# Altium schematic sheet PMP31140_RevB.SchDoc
size 431 x 279 mm; Date: Not shown in title block; ApprovedBy: Not shown in title block; CheckedBy: Not shown in title block; Author: Not shown in title block; CompanyName: Not shown in title block; Engineer: Not shown in title block; Organization: Not shown in title block; Address1: Not shown in title block; Address2: Not shown in title block; Address3: Not shown in title block; Address4: Not shown in title block; DocumentNumber: 1; Revision: Use project parameter SCH_Rev; SheetNumber: 1; SheetTotal: 1; PageSetup: Record=PageOptions¦CenterHorizontal=True¦CenterVertical=True¦PrintScale=1.00¦XCorrection=1.00¦YCorrection=1.00¦PrintKind=0¦BorderSize=5000000¦LeftOffset=0¦BottomOffset=0¦Orientation=2¦PaperLength=1000¦PaperWidth=1000¦Scale=100¦PaperSource=15¦PrintQuality=600¦MediaType=1¦DitherType=10¦PaperKind=Letter¦PrintScaleMode=1
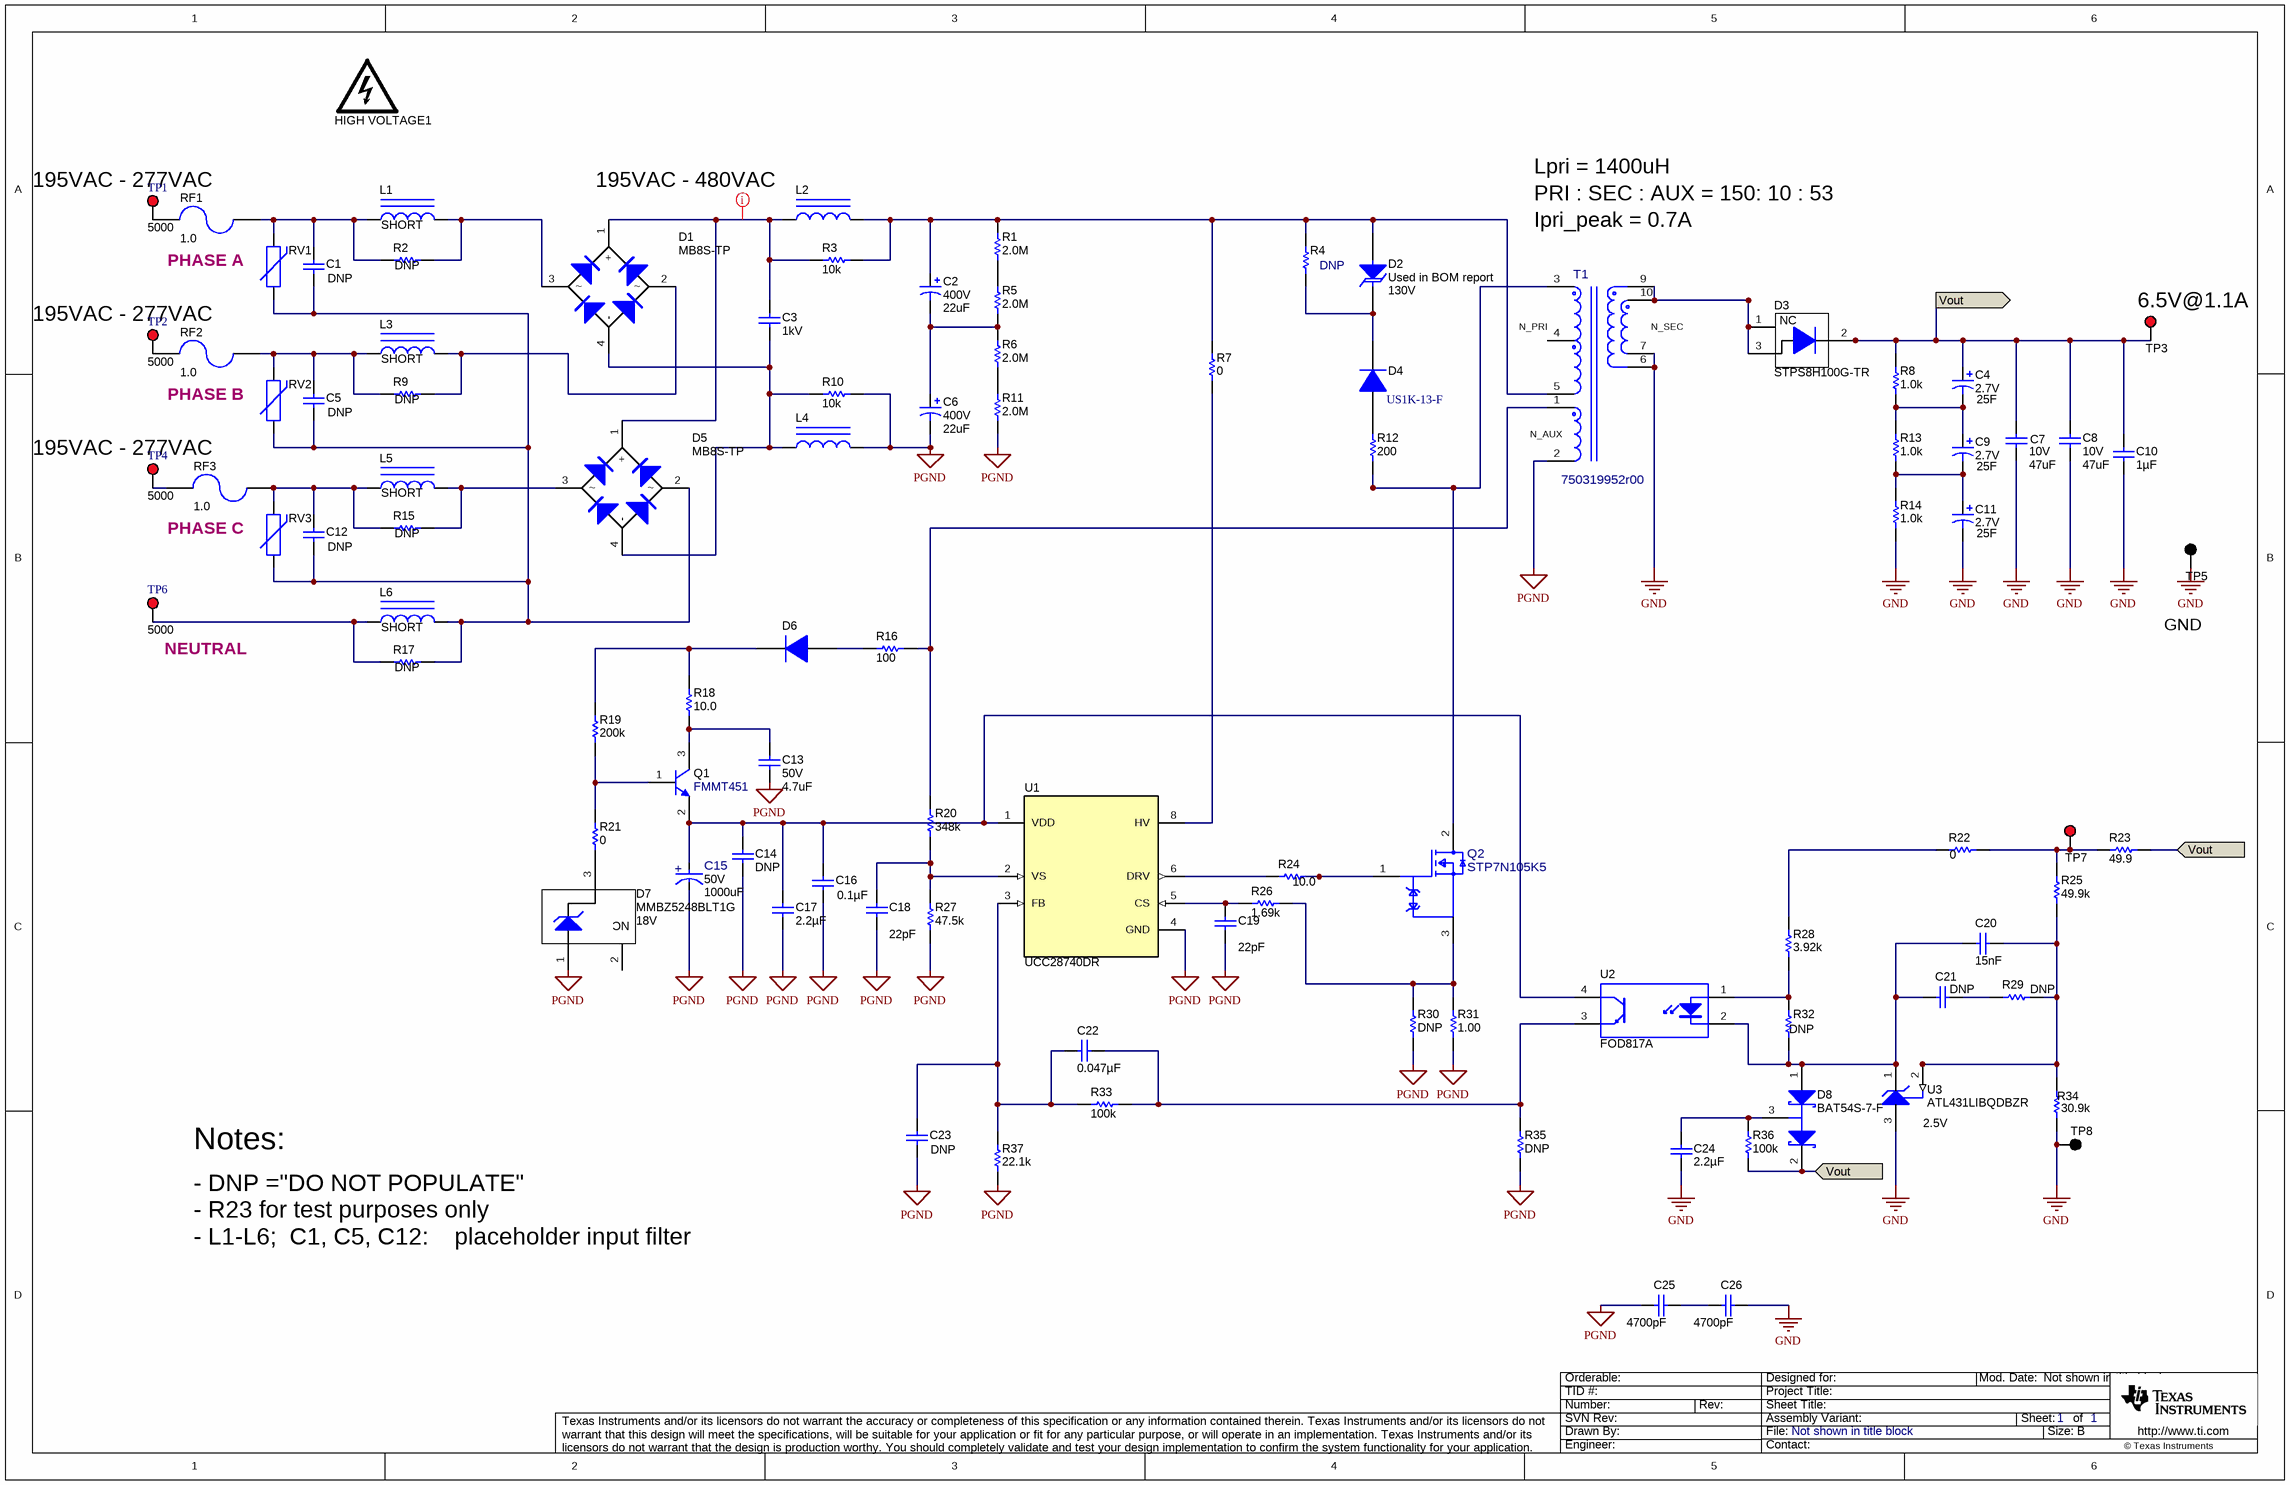
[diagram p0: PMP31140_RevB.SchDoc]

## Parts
C1  value DNP  [B32921_1300x1200x600]  (hidden comment: B32921C3104M)
C2  VDC_V: 400V  ValueDisplayed: 22uF  [KXG_1250x2000]  (hidden comment: EKXG401ELL220MK20S)
C3  VDC_V: 1kV  [B32652A_500x1050x1800]  (hidden comment: B32652A0103K)
C4  value 25F  VDC_V: 2.7V  [SCC_1600x2650]  (hidden comment: SCCU25B256SRB)
C5  value DNP  [B32921_1300x1200x600]  (hidden comment: B32921C3104M)
C6  VDC_V: 400V  ValueDisplayed: 22uF  [KXG_1250x2000]  (hidden comment: EKXG401ELL220MK20S)
C7  VDC_V: 10V  ValueDisplayed: 47uF  [1210_270]  (hidden comment: GRM32ER71A476KE15L)
C8  VDC_V: 10V  ValueDisplayed: 47uF  [1210_270]  (hidden comment: GRM32ER71A476KE15L)
C9  value 25F  VDC_V: 2.7V  [SCC_1600x2650]  (hidden comment: SCCU25B256SRB)
C10  Cap_F: 1µF  [0805_HV]  (hidden comment: GRM21BR71C105KA01L)
C11  value 25F  VDC_V: 2.7V  [SCC_1600x2650]  (hidden comment: SCCU25B256SRB)
C12  value DNP  [B32921_1300x1200x600]  (hidden comment: B32921C3104M)
C13  VDC_V: 50V  ValueDisplayed: 4.7uF  [1210_280]  (hidden comment: C3225X7R1H475K250AB)
C14  ValueDisplayed: DNP  [1206_180]  (hidden comment: C3216X7R1H475K160AC)
C15  VDC_V: 50V  ValueDisplayed: 1000uF  [FP-ECA-1HM102_RADIAL-MFG]  (hidden comment: ECA-1HM102)
C16  ValueDisplayed: 0.1µF  [0603]  (hidden comment: 06035C104KAT2A)
C17  ValueDisplayed: 2.2µF  [1206_180]  (hidden comment: C3216X7R1H475K160AC)
C18  ValueDisplayed: 22pF  [0603]  (hidden comment: 06035A220JAT2A)
C19  ValueDisplayed: 22pF  [0603]  (hidden comment: 06035A220JAT2A)
C20  Cap_F: 15nF  [0805_HV]  (hidden comment: C0805C153K5RACTU)
C21  value DNP  [0805_HV]  (hidden comment: Used in BOM report)
C22  ValueDisplayed: 0.047µF  [0603]  (hidden comment: 06035C333JAT2A)
C23  DNP  [0603]
C24  ValueDisplayed: 2.2µF  [0805_HV]  (hidden comment: GRM21BR71E105KA99L)
C25  value 4700pF  [KY_1000x500x1300]  (hidden comment: DE2E3KY472MB3BM02F)
C26  value 4700pF  [KY_1000x500x1300]  (hidden comment: DE2E3KY472MB3BM02F)
D1  MB8S-TP  [MBS-1]
D2  Used in BOM report  value 130V  [SMB]
D3  STPS8H100G-TR  [DDPAK]
D4  US1K-13-F  [SMA]
D5  MB8S-TP  [MBS-1]
D6  ES1D-13-F  [SMA]  (value not drawn)
D7  MMBZ5248BLT1G  value 18V  [SOT-23]
D8  BAT54S-7-F  [SOT-23]
HIGH_VOLTAGE1  DANGER HIGH VOLTAGE  [IEC_HighVoltage_Small]  (value not drawn)  (no BOM)
L1  value SHORT  [WE-TI_8075_STU]  (hidden comment: 744732331)
L2  744732331  [WE-TI_8075_STU]  (value not drawn)
L3  value SHORT  [WE-TI_8075_STU]  (hidden comment: 744732331)
L4  744732331  [WE-TI_8075_STU]  (value not drawn)
L5  value SHORT  [WE-TI_8075_STU]  (hidden comment: 744732331)
L6  value SHORT  [WE-TI_8075_STU]  (hidden comment: 744732331)
Q1  FMMT451  [SOT-23]
Q2  STP7N105K5  [FP-STP7N105K5_TO-220AB-MFG]
R1  ValueDisplayed: 2.0M  [0805_HV]  (hidden comment: CRCW08051M50JNEA)
R2  value DNP  [1206]  (hidden comment: CRCW120610K0JNEA)
R3  ValueDisplayed: 10k  [1206]  (hidden comment: CRCW120610K0JNEA)
R4  value DNP  [2512]  (hidden comment: Used in BOM report)
R5  ValueDisplayed: 2.0M  [0805_HV]  (hidden comment: CRCW08051M50JNEA)
R6  ValueDisplayed: 2.0M  [0805_HV]  (hidden comment: CRCW08051M50JNEA)
R7  ValueDisplayed: 0  [0805_HV]  (hidden comment: CRCW080530K0JNEA)
R8  ValueDisplayed: 1.0k  [1206]  (hidden comment: CRCW12061K00JNEA)
R9  value DNP  [1206]  (hidden comment: CRCW120610K0JNEA)
R10  ValueDisplayed: 10k  [1206]  (hidden comment: CRCW120610K0JNEA)
R11  ValueDisplayed: 2.0M  [0805_HV]  (hidden comment: CRCW08051M50JNEA)
R12  ValueDisplayed: 200  [2010]  (hidden comment: CRCW2010200RFKEF)
R13  ValueDisplayed: 1.0k  [1206]  (hidden comment: CRCW12061K00JNEA)
R14  ValueDisplayed: 1.0k  [1206]  (hidden comment: CRCW12061K00JNEA)
R15  value DNP  [1206]  (hidden comment: CRCW120610K0JNEA)
R16  ValueDisplayed: 100  [2010]  (hidden comment: CRCW2010100RJNEF)
R17  value DNP  [1206]  (hidden comment: CRCW120610K0JNEA)
R18  ValueDisplayed: 10.0  [0805_HV]  (hidden comment: CRCW080510R0FKEA)
R19  ValueDisplayed: 200k  [0805_HV]  (hidden comment: CRCW0805200KFKEA)
R20  ValueDisplayed: 348k  [0603]  (hidden comment: CRCW0603348KFKEA)
R21  ValueDisplayed: 0  [0603]  (hidden comment: Used in BOM report)
R22  ValueDisplayed: 0  [0603]  (hidden comment: CRCW06030000Z0EA)
R23  ValueDisplayed: 49.9  [0603]  (hidden comment: CRCW060349R9FKEA)
R24  value 10.0  [0805_HV]  (hidden comment: RC0805FR-0710RL)
R25  ValueDisplayed: 49.9k  [0603]  (hidden comment: CRCW060349K9FKEA)
R26  ValueDisplayed: 1.69k  [0603]  (hidden comment: CRCW06031K69FKEA)
R27  ValueDisplayed: 47.5k  [0603]  (hidden comment: CRCW060347K5FKEA)
R28  ValueDisplayed: 3.92k  [0603]  (hidden comment: CRCW06033K92FKEA)
R29  value DNP  [0603]  (hidden comment: Used in BOM report)
R30  ValueDisplayed: DNP  [0805_HV]
R31  ValueDisplayed: 1.00  [0805_HV]  (hidden comment: ERJ-6RQF1R0V)
R32  value DNP  [0603]  (hidden comment: Used in BOM report)
R33  ValueDisplayed: 100k  [0603]  (hidden comment: CRCW060330K1FKEA)
R34  ValueDisplayed: 30.9k  [0603]  (hidden comment: CRCW060330K9FKEA)
R35  value DNP  [0603]  (hidden comment: Used in BOM report)
R36  ValueDisplayed: 100k  [0805_HV]  (hidden comment: CRCW0805100KFKEA)
R37  ValueDisplayed: 22.1k  [0603]  (hidden comment: CRCW060310K0FKEA)
RF1  ValueDisplayed: 1.0  [SPP_1020x380]  (hidden comment: SPP1UL1R00JLF)
RF2  ValueDisplayed: 1.0  [SPP_1020x380]  (hidden comment: SPP1UL1R00JLF)
RF3  ValueDisplayed: 1.0  [SPP_1020x380]  (hidden comment: SPP1UL1R00JLF)
RV1  B72210S2301K101  [EPCOS_B72210S2301K101]  (value not drawn)
RV2  B72210S2301K101  [EPCOS_B72210S2301K101]  (value not drawn)
RV3  B72210S2301K101  [EPCOS_B72210S2301K101]  (value not drawn)
T1  750319952r00  [FP-750319952r00_PTH10_14MM6_22MM7-MFG]
TP1  5000  [Keystone5000]
TP2  5000  [Keystone5000]
TP3  5000  [Keystone5000]  (value not drawn)
TP4  5000  [Keystone5000]
TP5  5001  [Keystone5001]  (value not drawn)
TP6  5000  [Keystone5000]
TP7  5000  [Keystone5000]  (value not drawn)
TP8  5001  [Keystone5001]  (value not drawn)
U1  UCC28740DR  [D0007A_N]
U2  FOD817A  [DIP-4]
U3  ATL431LIBQDBZR  [DBZ0003A_N]

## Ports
Vout (in), Vout (out)

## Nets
GND: C7.2 C8.2 C10.2 C11.2(-) C24.2 C26.1 R14.1 R34.1 T1.6 T1.7 TP5.1 TP8.1 U3.3(ANODE)
PGND: C6.2(-) C13.2 C14.2 C15.1(CATHODE) C16.2 C17.2 C18.2 C19.2 C23.2 C25.2 D7.1(A) L4.2 R10.2 R11.1 R27.1 R30.1 R31.1 R35.2 R37.1 T1.2 U1.4(GND)
Vout: C4.1(+) C7.1 C8.1 C10.1 D3.2(K) D8.2(K) R8.2 R23.1 R36.1 TP3.1 ; port Vout
NetC1_1: C1.1 L1.1 R2.1 RF1.1 RV1.2
NetC1_2: C1.2 C5.2 C12.2 D5.2 L6.2 R17.2 RV1.1 RV2.1 RV3.1
NetC2_1: C2.1(+) D2.2(A) L2.2 R1.2 R3.2 R4.2 R7.2 T1.5
NetC2_2: C2.2(-) C6.1(+) R5.1 R6.2
NetC3_1: C3.1 D1.1(+) D5.1(+) L2.1 R3.1
NetC3_2: C3.2 D1.4(-) D5.4(-) L4.1 R10.1
NetC4_2: C4.2(-) C9.1(+) R8.1 R13.2
NetC5_1: C5.1 L3.1 R9.1 RF2.1 RV2.2
NetC9_2: C9.2(-) C11.1(+) R13.1 R14.2
NetC12_1: C12.1 L5.1 R15.1 RF3.1 RV3.2
NetC13_1: C13.1 Q1.3(C) R18.1
NetC14_1: C14.1 C15.2(ANODE) C16.1 C17.1 Q1.2(E) U1.1(VDD) U2.4(C)
NetC18_1: C18.1 R20.1 R27.2 U1.2(VS)
NetC19_1: C19.1 R26.1 U1.5(CS)
NetC20_1: C20.1 R25.1 R29.1 R34.2 U3.2(REF)
NetC20_2: C20.2 C21.1 D8.1(A) R32.1 U2.2(K) U3.1(CATHODE)
NetC21_2: C21.2 R29.2
NetC22_1: C22.1 R33.2 R35.1 U2.3(E)
NetC22_2: C22.2 C23.1 R33.1 R37.2 U1.3(FB)
NetC24_1: C24.1 D8.3(C) R36.2
NetC25_1: C25.1 C26.2
NetD1_2: D1.2 L3.2 R9.2
NetD1_3: D1.3 L1.2 R2.2
NetD2_1: D2.1(K) D4.1(K) R4.1
NetD3_1: D3.1(NC) D3.3(A) T1.9 T1.10
NetD4_2: D4.2(A) R12.2
NetD5_3: D5.3 L5.2 R15.2
NetD6_1: D6.1(K) R18.2 R19.2
NetD6_2: D6.2(A) R16.2
NetD7_3: D7.3(K) R21.1
NetL6_1: L6.1 R17.1 TP6.1
NetQ1_1: Q1.1(B) R19.1 R21.2
NetQ2_1: Q2.1(G) R24.2
NetQ2_2: Q2.2(D) R12.1 T1.3
NetQ2_3: Q2.3(S) R26.2 R30.2 R31.2
NetR1_1: R1.1 R5.2
NetR6_1: R6.1 R11.2
NetR7_1: R7.1 U1.8(HV)
NetR16_1: R16.1 R20.2 T1.1
NetR22_1: R22.1 R28.2
NetR22_2: R22.2 R23.2 R25.2 TP7.1
NetR24_1: R24.1 U1.6(DRV)
NetR28_1: R28.1 R32.2 U2.1(A)
NetRF1_2: RF1.2 TP1.1
NetRF2_2: RF2.2 TP2.1
NetRF3_2: RF3.2 TP4.1

Not connected (* = marked no-connect by the designer): D7 2(NC); T1 4

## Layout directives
rule Clearance Constraint [Clearance = 25mil]: NetC3_1

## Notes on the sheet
- Lpri = 1400uH
- (near TP1) 195VAC - 277VAC
- 195VAC - 480VAC
- PRI : SEC : AUX = 150: 10 : 53
- Ipri_peak = 0.7A
- PHASE A
- (near TP3) 6.5V@1.1A
- (near TP2) 195VAC - 277VAC
- (near T1) N_PRI
- (near T1) N_SEC
- PHASE B
- (near T1) N_AUX
- (near TP4) 195VAC - 277VAC
- PHASE C
- GND
- (near TP6) NEUTRAL
- Notes:
- (near U3) 2.5V
- - DNP ="DO NOT POPULATE"
- - R23 for test purposes only
- - L1-L6;  C1, C5, C12:    placeholder input filter

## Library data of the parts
C1 C5 C12 = CMP-0012393-1: CAP, Film, 0.1 uF, 305 V, +/- 20%, TH; Manufacturer: TDK; TaMin_C: -40°C; Polarized: N; SizeAreaWB_mm2: 120; Value1: Unknown; U/M: EA; TaMax_C: 110°C; SizeZ_mm: 12; SizeX_mm: 13; SizeY_mm: 6; Cap_Case: 13x12x6mm; Value2: 305V; SizeArea_mm2: 78; Cap_F: 100nF; AEC Category: Q200; ValueDisplayed: 0.1uF
C2 C6 = CMP-0010039-1: CAP, AL, 22 uF, 400 V, +/- 20%, TH; Manufacturer: Chemi-Con; TaMin_C: -40°C; Polarized: Y; SizeAreaWB_mm2: 210.25; Value1: Unknown; U/M: EA; Value: 22uF; TaMax_C: 105°C; SizeZ_mm: 21.5; SizeX_mm: 12.5; Cap_Case: 12.5x20; SizeArea_mm2: 156.25; CompType: Capacitor; Cap_F: 22µF; IRMS_A: 260mA; AEC Category: Q200
C3 = CMP-0012344-3: CAP, Film, 0.01 uF, 1000 V, +/- 10%, TH; Manufacturer: TDK; TaMin_C: -55°C; Polarized: N; SizeAreaWB_mm2: 140; Value1: Unknown; Value: 0.01uF; TaMax_C: 110°C; SizeZ_mm: 10.5; SizeX_mm: 18; SizeY_mm: 5; Cap_Case: 5x10.5x18; Value2: 1000V; SizeArea_mm2: 90; Cap_F: 10nF; AEC Category: Q200
C4 C9 C11 = CMP-0860272-1: CAP, Electric Double Layer, 25000000 µF, 2.7 V,+30/--10%, 0.027 ohm, TH; Manufacturer: AVX; AEC Qualified: N; Tolerance_%: 30%; SizeArea_mm2: 256; TaMax_C: 65°C; ESR_ohm: 27m; SizeZ_mm: 26.5; Cap_Case: 16x25mm; CompType: Capacitor; SizeY_mm: 16; SizeAreaWB_mm2: 324; TaMin_C: -40°C; AEC Category: Q200; Polarized: Y
C7 C8 = CMP-0009220-2: CAP, CERM, 47 uF, 10 V, +/- 10%, X7R, 1210; Manufacturer: MuRata; TaMin_C: -55°C; Polarized: N; SizeAreaWB_mm2: 14.7; Value1: Unknown; U/M: EA; Value: 47uF; TaMax_C: 125°C; SizeZ_mm: 2.7; SizeX_mm: 3.2; SizeY_mm: 2.5; Cap_Case: 1210; SizeArea_mm2: 8; Cap_F: 47µF; AEC Category: Q200
C10 = CMP-0008323-1: CAP, CERM, 1 uF, 16 V, +/- 10%, X7R, 0805; Manufacturer: MuRata; TaMin_C: -55°C; ESR_ohm: 3m; Polarized: N; SizeAreaWB_mm2: 6.75; Value1: 0.003 ohm; U/M: EA; Value: 1uF; TaMax_C: 125°C; SizeZ_mm: 1.45; SizeX_mm: 2; SizeY_mm: 1.25; Cap_Case: 0805; Value2: 16V; SizeArea_mm2: 2.5; AEC Category: Q200
C13 = CMP-0009124-1: CAP, CERM, 4.7 uF, 50 V, +/- 10%, X7R, 1210; Manufacturer: TDK; TaMin_C: -55°C; ESR_ohm: 3.166m; Polarized: N; SizeAreaWB_mm2: 14.7; Value1: 0.003166 ohm; U/M: EA; Value: 4.7uF; TaMax_C: 125°C; SizeZ_mm: 2.8; SizeX_mm: 3.2; SizeY_mm: 2.5; SizeArea_mm2: 8; Cap_F: 4.7µF; IRMS_A: 4.1331A; AEC Category: Q200
C14 = C2012X7R1H225K125AC: CAP, CERM, 2.2 µF, 50 V,+/- 10%, X7R, 0805; Manufacturer: TDK; Polarized: N; CompType: Capacitor; Value: DNP; U/M: EA; Cap_F: 0.0000022; Tolerance_%: 10; ESR_ohm: 0.00366; Value1: 0.00366 ohm; VDC_V: 50; Value2: 50V; IRMS_A: 3.41207; TaMin_C: -55; TaMax_C: 125; Cap_Case: 0805; SizeArea_mm2: 2.5; SizeAreaWB_mm2: 6.75; SizeX_mm: 2; SizeY_mm: 1.25; SizeZ_mm: 1.45; AEC Category: Q200; Green_Lifecycle: Active; Green_REACh: Passed
C15 = CMP-0088449-1: 1000µF 50V Aluminum Electrolytic Capacitors Radial; PartNumber: 860010678024; SizeZ_mm: 27mm; Life: 2000Hours; Tolerance_%: 20%; Cap_F: 1mF; Dissipation Factor: 12%; Leakage Current: 500uA; AEC Qualified: No; IRMS_A: 1.05A
C16 = 06035C104KAT2A: CAP, CERM, 0.1 µF, 50 V, +/- 10%, X7R, 0603; Manufacturer: AVX; Polarized: N; CompType: Capacitor; Value: 0.1uF; U/M: EA; Cap_F: 0.0000001; Tolerance_%: 10; Value1: Unknown; VDC_V: 50; Value2: 50V; TaMin_C: -55; TaMax_C: 125; SizeArea_mm2: 1.28; SizeAreaWB_mm2: 4.68; SizeX_mm: 1.6; SizeY_mm: 0.8; SizeZ_mm: 1; AEC Category: Q200
C17 = C2012X7R1H225K125AC: CAP, CERM, 2.2 µF, 50 V,+/- 10%, X7R, 0805; Manufacturer: TDK; Polarized: N; CompType: Capacitor; Value: 2.2uF; U/M: EA; Cap_F: 0.0000022; Tolerance_%: 10; ESR_ohm: 0.00366; Value1: 0.00366 ohm; VDC_V: 50; Value2: 50V; IRMS_A: 3.41207; TaMin_C: -55; TaMax_C: 125; Cap_Case: 0805; SizeArea_mm2: 2.5; SizeAreaWB_mm2: 6.75; SizeX_mm: 2; SizeY_mm: 1.25; SizeZ_mm: 1.45; AEC Category: Q200; Green_Lifecycle: Active; Green_REACh: Passed
C18 C19 = CMP-0006775-4: CAP, CERM, 22 pF, 50 V, +/- 5%, C0G/NP0, 0603; Manufacturer: AVX; TaMin_C: -55°C; ESR_ohm: 0.259; Polarized: N; SizeAreaWB_mm2: 4.68; Value1: 0.259 ohm; U/M: EA; Value: 22pF; TaMax_C: 125°C; SizeZ_mm: 1; SizeX_mm: 1.6; SizeY_mm: 0.8; Value2: 50V; SizeArea_mm2: 1.28; AEC Category: Q200
C20 = CMP-0007746-2: CAP, CERM, 0.015 uF, 50 V, +/- 10%, X7R, 0805; Manufacturer: Kemet; TaMin_C: -55°C; ESR_ohm: 0.124; Polarized: N; SizeAreaWB_mm2: 6.75; Value1: 0.124 ohm; U/M: EA; TaMax_C: 125°C; SizeZ_mm: 1.45; SizeX_mm: 2; SizeY_mm: 1.25; Cap_Case: 0805; Value2: 50V; SizeArea_mm2: 2.5; IRMS_A: 555mA; AEC Category: Q200
C21 = Capacitor: CAP, CERM, xxxF, xxV, [TempCo], xx%, [PackageReference]; Polarized: N; U/M: EA
C22 = C1608X7R1H473K080AA: CAP, CERM, 0.047 µF, 50 V,+/- 10%, X7R, 0603; Manufacturer: TDK; Polarized: N; CompType: Capacitor; Value: 0.047uF; U/M: EA; Cap_F: 0.000000047; Tolerance_%: 10; ESR_ohm: 0.049007; Value1: 0.049007 ohm; VDC_V: 50; Value2: 50V; IRMS_A: 0.767528; TaMin_C: -55; TaMax_C: 125; SizeArea_mm2: 1.28; SizeAreaWB_mm2: 4.68; SizeX_mm: 1.6; SizeY_mm: 0.8; SizeZ_mm: 1; AEC Category: Q200; Green_Lifecycle: NRND; Green_REACh: Passed
C23 = GRM188R71H222KA01D: CAP, CERM, 2200 pF, 50 V,+/- 10%, X7R, 0603; Manufacturer: MuRata; Polarized: N; CompType: Capacitor; U/M: EA; Cap_F: 0.0000000022; Tolerance_%: 10; VDC_V: 50; Value2: 50V; TaMin_C: -55; TaMax_C: 125; SizeArea_mm2: 1.28; SizeAreaWB_mm2: 4.68; SizeX_mm: 1.6; SizeY_mm: 0.8; SizeZ_mm: 1; AEC Category: Q200; Green_Lifecycle: Active; Green_REACh: Passed
C24 = GRM21BR71E225KA73L: CAP, CERM, 2.2 µF, 25 V,+/- 10%, X7R, 0805; Manufacturer: MuRata; Polarized: N; CompType: Capacitor; Value: 2.2uF; U/M: EA; Cap_F: 0.0000022; Tolerance_%: 10; ESR_ohm: 0.005; Value1: 0.005 ohm; VDC_V: 25; Value2: 25V; TaMin_C: -55; TaMax_C: 125; Cap_Case: 0805; SizeArea_mm2: 2.5; SizeAreaWB_mm2: 6.75; SizeX_mm: 2; SizeY_mm: 1.25; SizeZ_mm: 1.45; AEC Category: Q200; Green_Lifecycle: Active; Green_REACh: Passed
C25 C26 = DE2E3KY472MB3BM02F: CAP, CERM, 4700 pF, X1 250 VAC/Y2 300 VAC, +/- 20%, E, 10x5x13mm; Manufacturer: MuRata; Polarized: N; CompType: Capacitor; U/M: EA; Cap_F: 0.0000000047; Tolerance_%: 20; TaMin_C: -40; TaMax_C: 125; SizeArea_mm2: 50; SizeAreaWB_mm2: 84; SizeX_mm: 10; SizeY_mm: 5; SizeZ_mm: 13; AEC Category: Q200; AC_Safety: X1Y2; VAC_X: 250; VAC_Y: 300
D1 D5 = CMP-0029235-1: Diode, Switching-Bridge, 800 V, 0.5 A, TO269AA; Manufacturer: Micro Commercial Components; Io_A: 500mA; Green_Lifecycle: Not Set; SizeAreaWB_mm2: 58.725; Vr_V: 800V; Green_REACh: Incomplete; Value1: 0.5A; TJmax_C: 150°C; U/M: EA; Value: 800V; SizeZ_mm: 2.7; SizeX_mm: 6.7; SizeY_mm: 4.75; Vf_V: 1V; SizeArea_mm2: 31.825; AEC Category: Q101
D2 = SMBJ120A-13-F: Diode, TVS, Uni, 130 V, 193 Vc, SMB; PartNumber: SMBJ130A-13-F; Manufacturer: Diodes Inc.; U/M: EA; Power_W: 5; Vr_V: 120; Value1: 5W; SizeAreaWB_mm2: 44.156; SizeArea_mm2: 21.336; SizeX_mm: 5.6; SizeY_mm: 3.81; SizeZ_mm: 2.6; AEC Category: Q101; Green_Lifecycle: Active; Green_REACh: Passed
D3 = CMP-0028896-2: Diode, Schottky, 100 V, 8 A, DDPAK; Manufacturer: STMicroelectronics; Io_A: 8A; RJC_CperW: 1.6; SizeZ_mm: 4.445; Green_REACh: Incomplete; AEC Category: Q101; SizeArea_mm2: 154.8892; AEC Qualified: N; Value: 100V; TJmax_C: 175°C; U/M: EA; SizeY_mm: 10.16; Green_Lifecycle: Not Set; SizeAreaWB_mm2: 209.6992; SizeX_mm: 15.245; Vf_V: 710mV; Value2: 0.71V
D4 = US1K-13-F: Diode, Fast Rectifier, 800 V, 1 A, SMA; Manufacturer: Diodes Inc.; U/M: EA; Vf_V: 1.7; Value: 800V; Value1: 1A; Value2: 1.7V; Io_A: 1; Vr_V: 800; TJmax_C: 150; SizeAreaWB_mm2: 37.3428; SizeArea_mm2: 16.3228; SizeX_mm: 5.59; SizeY_mm: 2.92; SizeZ_mm: 2.87; AEC Category: Q101; Green_Lifecycle: Not Set; Green_REACh: Incomplete
D6 = ES1D-13-F: Diode, Ultrafast, 200 V, 1 A, SMA; Manufacturer: Diodes Inc.; U/M: EA; Vf_V: 0.92; Value: 200V; Value1: 1A; Value2: 0.92V; Io_A: 1; Vr_V: 200; TJmax_C: 150; RJC_CperW: 25; SizeAreaWB_mm2: 37.3428; SizeArea_mm2: 16.3228; SizeX_mm: 5.59; SizeY_mm: 2.92; SizeZ_mm: 2.87; AEC Category: Q101; Green_Lifecycle: Active; Green_REACh: Passed
D7 = MMBZ5248BLT1G: Diode, Zener, 18 V, 225 mW, SOT-23; Manufacturer: ON Semiconductor; U/M: EA; Power_W: 0.225; Vz_V: 18; Value1: 0.225W; RJA_CperW: 556; SizeAreaWB_mm2: 14; SizeArea_mm2: 7.5; SizeX_mm: 2.5; SizeY_mm: 3; SizeZ_mm: 1.1; AEC Category: Q101
D8 = BAT54S-7-F: Diode, Schottky, 30 V, 0.2 A, SOT-23; Manufacturer: Diodes Inc.; U/M: EA; Vf_V: 0.65; Value: 30V; Value1: 0.2A; Value2: 0.65V; Io_A: 0.2; Vr_V: 30; TJmax_C: 125; SizeAreaWB_mm2: 14; SizeArea_mm2: 7.5; SizeX_mm: 2.5; SizeY_mm: 3; SizeZ_mm: 1.1; AEC Category: Q101; Green_Lifecycle: Active; Green_REACh: Passed
HIGH_VOLTAGE1 = IEC_HighVoltage: IEC 61010-1 High Voltage Warning; SymbolCreator: a0412235
L1 L3 L5 L6 = CMP-0064737-1: Inductor, Unshielded Drum Core, Metal Composite, 330 uH; Manufacturer: Wurth Elektronik; Isat: 0.75A @ 10% inductance drop; Irms: 0.42A @ 40C rise; SizeAreaWB_mm2: 132.25; DCR_ohm: 2.2; Value1: 2.2 ohm; Imax_A: 420mA; SizeZ_mm: 8; SizeX_mm: 9.5; SizeArea_mm2: 90.25; Ind_H: 330µH; AEC Qualified: N; AEC Category: Q200; ValueDisplayed: 330uH
L2 L4 = CMP-0064737-1: Inductor, Unshielded Drum Core, Metal Composite, 330 uH; Manufacturer: Wurth Elektronik; Isat: 0.75A @ 10% inductance drop; Irms: 0.42A @ 40C rise; SizeAreaWB_mm2: 132.25; DCR_ohm: 2.2; Value1: 2.2 ohm; Value: 330uH; Imax_A: 420mA; SizeZ_mm: 8; SizeX_mm: 9.5; SizeArea_mm2: 90.25; Ind_H: 330µH; AEC Qualified: N; AEC Category: Q200
Q1 = CMP-0000467-1: Transistor, NPN, 60 V,; Manufacturer: Diodes Inc.; TaMax_C: 150°C; Value2: 900; Value1: 1.5 A; Vcesat1_V: 160mV; SizeX_mm: 2.5; SizeY_mm: 3; TaMin_C: -55°C; IcRated_A: 1.5A; CompType: BJT; SizeZ_mm: 1.1; AEC Qualified: Y; Value: 60 V; SizeArea_mm2: 7.5; NPN: 1; Vceo_V: 80V; PNP: 0; AEC Category: Q101; SizeAreaWB_mm2: 14; U/M: EA
Q2 = CMP-0088481-1: N-Channel 1050V 4A (Tc) 110W (Tc) Through Hole TO-220; Manufacturer: STMicroelectronics; QgTyp_nC: 11nC @ 10V; Standoff Height: 3.5mm; Threshold Vgs Max: 5V; SizeZ_mm: 19.68mm; Reverse Recovery Time: 370ns; Rdson45_ohm: 1.4; Turn Off Delay Time: 43ns; VdsMax_V: 1.6V; Pulse Drain Current: 16A; Threshold Vgs Min: 3V; Rthja Max: 62.5°C/W; Number Of Channels: 1; AEC Qualified: No; Input Capacitace At Vds: 380pF @ 100V; Reverse Recovery Charge: 3000nC; ChMode: False; TJmax_C: +150°C; Vgs_V: 30V; Turn On Delay Time: 17.5ns
R1 R5 R6 R11 = CRCW08052M00JNEA: RES, 2.0 M, 5%, 0.125 W, 0805; Manufacturer: Vishay-Dale; CompType: Resistor; Value: 2.0Meg; Res_ohm: 2000000; Value_Code: 2M00; Tolerance_%: 5; Power_W: 0.125; Value2: 0.125W; VDC_V: 150; TempCo: 200 ppm/C; SizeArea_mm2: 2.5; SizeX_mm: 2; SizeY_mm: 1.25; SizeZ_mm: 1.45; EIA_Code: E24; U/M: EA; AEC Category: Q200
R2 R9 R15 R17 = CMP-0018576-1: RES, 10 k, 5%, 0.25 W, 1206; Manufacturer: Vishay-Dale; Power_W: 250mW; TempCo: 200 ppm/C; Value_Code: 10k0; U/M: EA; EIA_Code: E24; Res_ohm: 10k; SizeX_mm: 3.2; SizeY_mm: 1.6; SizeZ_mm: 1.35; Value2: 0.25W; SizeArea_mm2: 5.12; VDC_V: 200V; AEC Category: Q200
R3 R10 = CMP-0018576-1: RES, 10 k, 5%, 0.25 W, 1206; Manufacturer: Vishay-Dale; Power_W: 250mW; TempCo: 200 ppm/C; Value_Code: 10k0; U/M: EA; Value: 10k; EIA_Code: E24; SizeX_mm: 3.2; SizeY_mm: 1.6; SizeZ_mm: 1.35; Value2: 0.25W; SizeArea_mm2: 5.12; VDC_V: 200V; AEC Category: Q200
R4 R29 R32 R35 = Resistor: RES, xxx ohm, x%, xW, [PackageReference]; U/M: EA
R7 = CRCW080530K0JNEA: RES, 30 k, 5%, 0.125 W, 0805; Manufacturer: Vishay-Dale; CompType: Resistor; Value: 0; Res_ohm: 30000; Value_Code: 30k0; Tolerance_%: 5; Power_W: 0.125; Value2: 0.125W; VDC_V: 150; TempCo: 200 ppm/C; SizeArea_mm2: 2.5; SizeX_mm: 2; SizeY_mm: 1.25; SizeZ_mm: 1.45; EIA_Code: E24; U/M: EA; AEC Category: Q200; Green_Lifecycle: Active; Green_REACh: Passed
R8 R13 R14 = CMP-0018603-2: RES, 1.0 k, 5%, 0.25 W, 1206; Manufacturer: Vishay-Dale; Power_W: 250mW; TempCo: 200 ppm/C; Value_Code: 1k00; U/M: EA; Value: 1.0k; EIA_Code: E24; Res_ohm: 1k; SizeX_mm: 3.2; SizeY_mm: 1.6; SizeZ_mm: 1.35; Value2: 0.25W; SizeArea_mm2: 5.12; VDC_V: 200V; AEC Category: Q200
R12 = CRCW2010200RFKEF: RES, 200, 1%, 0.75 W, AEC-Q200 Grade 0, 2010; Manufacturer: Vishay-Dale; CompType: Resistor; Value: 200; Value_Code: 200R; Tolerance_%: 1; Power_W: 0.75; Value2: 0.75W; VDC_V: 400; TempCo: 100 ppm/C; SizeArea_mm2: 12.5; SizeX_mm: 5; SizeY_mm: 2.5; SizeZ_mm: 1.66; EIA_Code: E96; U/M: EA; AEC Category: Q200; AEC Qualified: Y; AEC Grade: 0
R16 = CRCW2010100RJNEF: RES, 100, 5%, 0.75 W, AEC-Q200 Grade 0, 2010; Manufacturer: Vishay-Dale; CompType: Resistor; Value: 100; Value_Code: 100R; Tolerance_%: 5; Power_W: 0.75; Value2: 0.75W; VDC_V: 400; TempCo: 200 ppm/C; SizeArea_mm2: 12.5; SizeY_mm: 2.5; SizeZ_mm: 1.66; EIA_Code: E24; U/M: EA; AEC Category: Q200; AEC Qualified: Y; AEC Grade: 0
R18 = CMP-0020847-3: RES, 10.0, 1%, 0.125 W, AEC-Q200 Grade 0, 0805; Manufacturer: Vishay-Dale; Power_W: 125mW; TempCo: 100 ppm/C; Value_Code: 10R0; Value: 10.0; EIA_Code: E96; Res_ohm: 10; SizeX_mm: 2; SizeY_mm: 1.25; SizeZ_mm: 1.45; Value2: 0.125W; SizeArea_mm2: 2.5; AEC Qualified: Y; VDC_V: 150V; AEC Category: Q200; AEC Grade: 0
R19 = CMP-0021038-1: RES, 200 k, 1%, 0.125 W, 0805; Manufacturer: Vishay-Dale; Power_W: 125mW; TempCo: 100 ppm/C; U/M: EA; Value: 200k; EIA_Code: E96; SizeX_mm: 2; SizeY_mm: 1.25; SizeZ_mm: 1.45; Value2: 0.125W; SizeArea_mm2: 2.5; VDC_V: 150V; AEC Category: Q200
R20 = CMP-0022344-3: RES, 348 k, 1%, 0.1 W, 0603; Manufacturer: Vishay-Dale; Power_W: 100mW; TempCo: 100 ppm/C; U/M: EA; Value: 348k; EIA_Code: E96; SizeX_mm: 1.6; SizeY_mm: 0.8; SizeZ_mm: 1; Value2: 0.1W; SizeArea_mm2: 1.28; VDC_V: 75V; AEC Category: Q200
R21 = CRCW06030000Z0EA: RES, 0, 5%, 0.1 W, 0603; Manufacturer: Vishay-Dale; CompType: Resistor; Value: 0; Value_Code: 0000; Tolerance_%: 5; Power_W: 0.1; Value2: 0.1W; VDC_V: 75; TempCo: 200 ppm/C; SizeArea_mm2: 1.28; SizeX_mm: 1.6; SizeY_mm: 0.8; SizeZ_mm: 1; EIA_Code: E24; U/M: EA; AEC Category: Q200; Green_Lifecycle: Active; Green_REACh: Passed
R22 = CRCW06030000Z0EA: RES, 0, 5%, 0.1 W, 0603; Manufacturer: Vishay-Dale; CompType: Resistor; Value: 0; Value_Code: 0000; Tolerance_%: 5; Power_W: 0.1; Value2: 0.1W; VDC_V: 75; TempCo: 200 ppm/C; SizeArea_mm2: 1.28; SizeX_mm: 1.6; SizeY_mm: 0.8; SizeZ_mm: 1; EIA_Code: E24; U/M: EA; AEC Category: Q200
R23 = CRCW060349R9FKEA: RES, 49.9, 1%, 0.1 W, 0603; Manufacturer: Vishay-Dale; CompType: Resistor; Value: 49.9; Value_Code: 49R9; Tolerance_%: 1; Power_W: 0.1; Value2: 0.1W; VDC_V: 75; TempCo: 100 ppm/C; SizeArea_mm2: 1.28; SizeX_mm: 1.6; SizeY_mm: 0.8; EIA_Code: E96; U/M: EA; AEC Category: Q200
R24 = RC0805FR-0710RL: RES, 10.0, 1%, 0.125 W, 0805; Manufacturer: Yageo America; CompType: Resistor; Res_ohm: 10; Value_Code: 10R0; Tolerance_%: 1; Power_W: 0.125; Value2: 0.125W; VDC_V: 150; TempCo: 200 ppm/C; SizeArea_mm2: 2.5; SizeX_mm: 2; SizeY_mm: 1.25; SizeZ_mm: 1.45; EIA_Code: E96; U/M: EA; AEC Category: Q200; Green_Lifecycle: Active; Green_REACh: Passed
R25 = CMP-0022447-3: RES, 49.9 k, 1%, 0.1 W, 0603; Manufacturer: Vishay-Dale; Power_W: 100mW; TempCo: 100 ppm/C; Value_Code: 49k9; U/M: EA; Value: 49.9k; EIA_Code: E96; SizeX_mm: 1.6; SizeY_mm: 0.8; SizeZ_mm: 1; Value2: 0.1W; SizeArea_mm2: 1.28; VDC_V: 75V; AEC Category: Q200
R26 = CMP-0022131-1: RES, 1.69 k, 1%, 0.1 W, 0603; Manufacturer: Vishay-Dale; Power_W: 100mW; TempCo: 100 ppm/C; Value_Code: 1k69; U/M: EA; Value: 1.69k; EIA_Code: E96; SizeX_mm: 1.6; SizeY_mm: 0.8; SizeZ_mm: 1; Value2: 0.1W; SizeArea_mm2: 1.28; VDC_V: 75V; AEC Category: Q200
R27 = CMP-0022439-1: RES, 47.5 k, 1%, 0.1 W, 0603; Manufacturer: Vishay-Dale; Power_W: 100mW; TempCo: 100 ppm/C; Value_Code: 47k5; U/M: EA; Value: 47.5k; EIA_Code: E96; SizeX_mm: 1.6; SizeY_mm: 0.8; SizeZ_mm: 1; Value2: 0.1W; SizeArea_mm2: 1.28; VDC_V: 75V; AEC Category: Q200
R28 = CMP-0022383-3: RES, 3.92 k, 1%, 0.1 W, 0603; Manufacturer: Vishay-Dale; Power_W: 100mW; TempCo: 100 ppm/C; Value_Code: 3k92; U/M: EA; Value: 3.92k; EIA_Code: E96; SizeX_mm: 1.6; SizeY_mm: 0.8; SizeZ_mm: 1; Value2: 0.1W; SizeArea_mm2: 1.28; VDC_V: 75V; AEC Category: Q200
R30 = CMP-0021828-1: RES, 2.20, 1%, 0.125 W, 0805; Manufacturer: Panasonic; Power_W: 125mW; TempCo: 200 ppm/C; Value_Code: 2R20; U/M: EA; Value: DNP; SizeX_mm: 2; SizeY_mm: 1.25; SizeZ_mm: 1.45; Value2: 0.125W; SizeArea_mm2: 2.5; AEC Category: Q200
R31 = CMP-0021824-2: RES, 1.00, 1%, 0.125 W, 0805; Manufacturer: Panasonic; Power_W: 125mW; TempCo: 200 ppm/C; Value_Code: 1R00; U/M: EA; Value: 1.00; EIA_Code: E96; Res_ohm: 1; SizeX_mm: 2; SizeY_mm: 1.25; SizeZ_mm: 1.45; Value2: 0.125W; SizeArea_mm2: 2.5; AEC Category: Q200
R33 = CRCW0603100KFKEA: RES, 100 k, 1%, 0.1 W, 0603; Manufacturer: Vishay-Dale; CompType: Resistor; Value: 100k; Res_ohm: 100000; Tolerance_%: 1; Power_W: 0.1; Value2: 0.1W; VDC_V: 75; TempCo: 100 ppm/C; SizeArea_mm2: 1.28; SizeX_mm: 1.6; SizeY_mm: 0.8; EIA_Code: E96; U/M: EA; AEC Category: Q200; Green_Lifecycle: Active; Green_REACh: Passed
R34 = CMP-0022325-3: RES, 30.9 k, 1%, 0.1 W, 0603; Manufacturer: Vishay-Dale; Power_W: 100mW; TempCo: 100 ppm/C; Value_Code: 30k9; U/M: EA; Value: 30.9k; EIA_Code: E96; SizeX_mm: 1.6; SizeY_mm: 0.8; SizeZ_mm: 1; Value2: 0.1W; SizeArea_mm2: 1.28; VDC_V: 75V; AEC Category: Q200
R36 = CRCW0805100KFKEA: RES, 100 k, 1%, 0.125 W, 0805; Manufacturer: Vishay-Dale; CompType: Resistor; Value: 100k; Res_ohm: 100000; Tolerance_%: 1; Power_W: 0.125; Value2: 0.125W; VDC_V: 150; TempCo: 100 ppm/C; SizeArea_mm2: 2.5; SizeX_mm: 2; SizeY_mm: 1.25; SizeZ_mm: 1.45; EIA_Code: E96; U/M: EA; AEC Category: Q200; Green_Lifecycle: Active; Green_REACh: Passed
R37 = CRCW060322K1FKEA: RES, 22.1 k, 1%, 0.1 W, 0603; Manufacturer: Vishay-Dale; CompType: Resistor; Value: 22.1k; Res_ohm: 22100; Value_Code: 22k1; Tolerance_%: 1; Power_W: 0.1; Value2: 0.1W; VDC_V: 75; TempCo: 100 ppm/C; SizeArea_mm2: 1.28; SizeX_mm: 1.6; SizeY_mm: 0.8; EIA_Code: E96; U/M: EA; AEC Category: Q200; Green_Lifecycle: Active; Green_REACh: Passed
RF1-RF3 = CMP-0014490-1: RES, 1.0, 5%, 1 W, TH, 2-Leads, Axial, Dia 3.8mm, Pin Spaing 15.2mm; Manufacturer: TT Electronics/IRC; Power_W: 1W; TempCo: 300 ppm/C; Value_Code: 1R00; U/M: EA; Value: 1.0; EIA_Code: E24; Res_ohm: 1; CompType: Resistor; AEC Category: Q200
RV1-RV3 = CMP-0001853-2: SIOV Metal Oxide Leaded Varistor, 300VAC, 3500A, TH; Manufacturer: TDK; Value: TBD
T1 = CMP-0094613-1: TRANSFORMER; Manufacturer: Wurth; Ind_H: 1.4mH; Rsec1_ohm: 16m; Voltage_Isolation_Vrms: 4kV; Frequency_Fixed: 65kHz; AEC Qualified: No; SizeZ_mm: 25.3mm; DCR_ohm: 3.68; Ns1toNp: 15:1
TP1 TP2 TP4 TP6 = CMP-0055137-1: Test Point, Miniature, Red, TH; Manufacturer: Keystone; CNHeader: FALSE; Green_Lifecycle: Active; Green_REACh: Passed; ContactFinish: Silver; CT: TRUE
TP3 TP7 = 5000: Test Point, Miniature, Red, TH; Manufacturer: Keystone; CompType: Test Point Loop; ContactFinish: Silver
TP5 TP8 = 5001: Test Point, Miniature, Black, TH; Manufacturer: Keystone; CompType: Test Point Loop; ContactFinish: Silver
U1 = UCC28740DR: Constant-Voltage, Constant-Current Flyback Controller Using Opto-Coupler Feedback, D0007A; Manufacturer: Texas Instruments; SymbolCreator: a0412235; SizeArea_mm2: 29.4; SizeAreaWB_mm2: 55.2; SizeX_mm: 6; SizeY_mm: 4.9; SizeZ_mm: 1.75; CompType: IC; U/M: EA
U2 = FOD817A: Optocoupler, 5 kV, 80-160% CTR, TH; Manufacturer: Fairchild Semiconductor; CTR (Min): 80%; CTR (Max): 160%; Voltage_Isolation_Vrms: 5000V
U3 = CMP-0084731-1: High Bandwidth Low-Iq Programmable Shunt Regulator, DBZ0003A (SOT-23-3); Manufacturer: Texas Instruments; CompType: IC; SizeX_mm: 2.5; AEC Category: Q200; SizeY_mm: 3; SizeArea_mm2: 7.5; AEC Qualified: N; SizeZ_mm: 1.12; SizeAreaWB_mm2: 14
